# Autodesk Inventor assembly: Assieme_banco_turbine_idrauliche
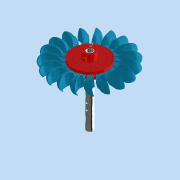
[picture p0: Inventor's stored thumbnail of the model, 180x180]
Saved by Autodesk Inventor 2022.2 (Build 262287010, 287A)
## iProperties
Created: 2025-03
Part Number: Assieme_banco_turbine_idrauliche
Document SubType Name: Assembly
Designer: 18907419
Title: Assieme_banco_turbine_idrauliche.stp
Author: R5800u
Sending System: Autodesk Inventor 2025
Preprocessor: ST-DEVELOPER v20
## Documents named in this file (2)
- C:\Users\18907419\Desktop\turgo\Assieme_banco_turbine_idrauliche.iam
- C:\Users\18907419\Desktop\turgo\Assieme_turgo.iam
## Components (1 placed, 1 different names)
1. Assieme_turgo:1 [sub-assembly]
